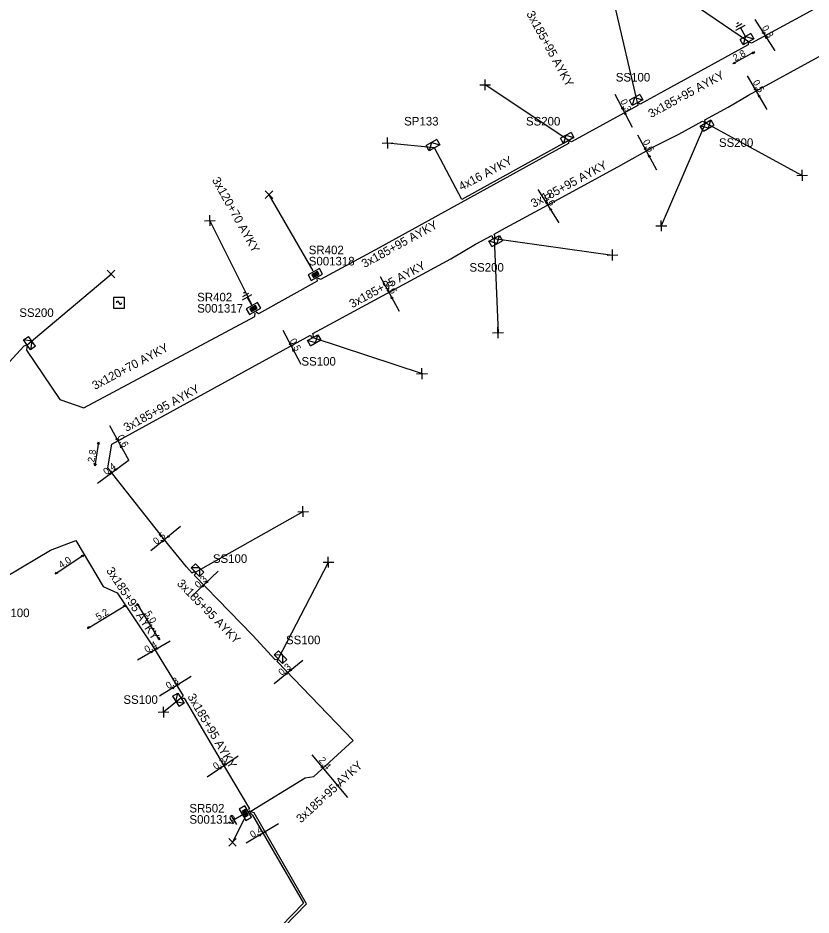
# Model space of a CAD drawing. Extents: x -762500 to -761285, y -1155006 to -1154135.
# Drawn here: x -761820.3 to -761728.2, y -1154763.7 to -1154659.6 of the extents above; entities that cross this region are included whole.
import ezdxf

# ---------------------------------------------------------------- set-up
doc = ezdxf.new("R2010")
doc.units = 0
for name, color, linetype in [('Vrstva 15', 7, 'Continuous'), ('Vrstva 28', 7, 'Continuous'), ('Vrstva 29', 7, 'Continuous'), ('Vrstva 30', 7, 'Continuous'), ('Vrstva 31', 7, 'Continuous'), ('Vrstva 33', 7, 'Continuous'), ('Vrstva 34', 7, 'Continuous'), ('Vrstva 40', 7, 'Continuous'), ('Vrstva 5', 7, 'Continuous'), ('Vrstva 59', 7, 'Continuous'), ('Vrstva 6', 7, 'Continuous')]:
    doc.layers.add(name, color=color, linetype=linetype)

msp = doc.modelspace()

# ---------------------------------------------------------------- linework, layer by layer
at = {"layer": 'Vrstva 15'}
for points in [[(-761736.967, -1154661.052), (-761735.874, -1154660.446)], [(-761736.906, -1154660.664), (-761736.218, -1154660.282)], [(-761736.84, -1154660.267), (-761736.723, -1154660.203)], [(-761736.723, -1154660.203), (-761736.611, -1154660.14)], [(-761735.814, -1154661.842), (-761736.42, -1154660.749)], [(-761794.227, -1154692.312), (-761793.134, -1154691.706)], [(-761794.166, -1154691.924), (-761793.478, -1154691.542)], [(-761794.099, -1154691.527), (-761793.983, -1154691.462)], [(-761793.983, -1154691.462), (-761793.871, -1154691.4)], [(-761793.074, -1154693.102), (-761793.68, -1154692.009)], [(-761794.126, -1154751.994), (-761795.198, -1154752.638)], [(-761795.734, -1154752.96), (-761795.8, -1154752.85)], [(-761795.665, -1154753.074), (-761795.734, -1154752.96)], [(-761795.266, -1154753.126), (-761795.671, -1154752.451)], [(-761794.876, -1154753.173), (-761795.52, -1154752.102)]]:
    msp.add_lwpolyline(points, dxfattribs=at)
at = {"layer": 'Vrstva 28'}
for points in [[(-761785.287, -1154688.704), (-761786.599, -1154689.432)], [(-761786.599, -1154689.432), (-761786.236, -1154690.088)], [(-761786.236, -1154690.088), (-761784.924, -1154689.36)], [(-761785.521, -1154689.05), (-761786.172, -1154689.411)], [(-761786.172, -1154689.411), (-761785.989, -1154689.741)], [(-761785.54, -1154689.114), (-761786.108, -1154689.429)], [(-761786.108, -1154689.429), (-761785.971, -1154689.677)], [(-761785.558, -1154689.179), (-761786.044, -1154689.448)], [(-761786.044, -1154689.448), (-761785.952, -1154689.613)], [(-761785.989, -1154689.741), (-761785.338, -1154689.381)], [(-761785.577, -1154689.243), (-761785.979, -1154689.466)], [(-761785.979, -1154689.466), (-761785.934, -1154689.549)], [(-761785.971, -1154689.677), (-761785.402, -1154689.362)], [(-761785.952, -1154689.613), (-761785.467, -1154689.344)], [(-761785.934, -1154689.549), (-761785.531, -1154689.325)], [(-761785.59, -1154689.304), (-761785.92, -1154689.487)], [(-761785.531, -1154689.325), (-761785.577, -1154689.243)], [(-761785.467, -1154689.344), (-761785.558, -1154689.179)], [(-761785.402, -1154689.362), (-761785.54, -1154689.114)], [(-761785.338, -1154689.381), (-761785.521, -1154689.05)], [(-761784.924, -1154689.36), (-761785.287, -1154688.704)], [(-761792.468, -1154692.644), (-761793.78, -1154693.372)], [(-761792.104, -1154693.3), (-761792.468, -1154692.644)], [(-761793.78, -1154693.372), (-761793.416, -1154694.028)], [(-761793.416, -1154694.028), (-761792.104, -1154693.3)], [(-761792.702, -1154692.99), (-761793.353, -1154693.351)], [(-761793.353, -1154693.351), (-761793.169, -1154693.681)], [(-761792.72, -1154693.054), (-761793.288, -1154693.369)], [(-761793.288, -1154693.369), (-761793.151, -1154693.617)], [(-761792.739, -1154693.119), (-761793.224, -1154693.388)], [(-761793.224, -1154693.388), (-761793.133, -1154693.553)], [(-761793.169, -1154693.681), (-761792.519, -1154693.321)], [(-761792.757, -1154693.183), (-761793.16, -1154693.406)], [(-761793.16, -1154693.406), (-761793.114, -1154693.489)], [(-761793.151, -1154693.617), (-761792.583, -1154693.302)], [(-761793.133, -1154693.553), (-761792.647, -1154693.284)], [(-761793.114, -1154693.489), (-761792.711, -1154693.265)], [(-761792.77, -1154693.244), (-761793.101, -1154693.427)], [(-761792.711, -1154693.265), (-761792.757, -1154693.183)], [(-761792.647, -1154693.284), (-761792.739, -1154693.119)], [(-761792.583, -1154693.302), (-761792.72, -1154693.054)], [(-761792.519, -1154693.321), (-761792.702, -1154692.99)], [(-761793.962, -1154751.017), (-761794.605, -1154751.403)], [(-761794.605, -1154751.403), (-761793.833, -1154752.689)], [(-761793.928, -1154751.43), (-761794.252, -1154751.625)], [(-761794.252, -1154751.625), (-761793.868, -1154752.263)], [(-761793.944, -1154751.495), (-761794.187, -1154751.641)], [(-761794.187, -1154751.641), (-761793.852, -1154752.198)], [(-761793.96, -1154751.56), (-761794.122, -1154751.657)], [(-761794.122, -1154751.657), (-761793.836, -1154752.133)], [(-761793.976, -1154751.625), (-761794.057, -1154751.673)], [(-761794.057, -1154751.673), (-761793.82, -1154752.068)], [(-761793.995, -1154751.685), (-761793.801, -1154752.009)], [(-761793.739, -1154752.02), (-761793.976, -1154751.625)], [(-761793.19, -1154752.303), (-761793.962, -1154751.017)], [(-761793.674, -1154752.036), (-761793.96, -1154751.56)], [(-761793.609, -1154752.052), (-761793.944, -1154751.495)], [(-761793.544, -1154752.068), (-761793.928, -1154751.43)], [(-761793.852, -1154752.198), (-761793.609, -1154752.052)], [(-761793.836, -1154752.133), (-761793.674, -1154752.036)], [(-761793.82, -1154752.068), (-761793.739, -1154752.02)], [(-761793.868, -1154752.263), (-761793.544, -1154752.068)], [(-761793.833, -1154752.689), (-761793.19, -1154752.303)]]:
    msp.add_lwpolyline(points, dxfattribs=at)
at = {"layer": 'Vrstva 31'}
for points in [[(-761735.224, -1154661.447), (-761736.449, -1154662.126)], [(-761735.224, -1154661.447), (-761734.885, -1154662.059), (-761736.109, -1154662.738), (-761736.449, -1154662.126)], [(-761735.837, -1154661.786), (-761736.109, -1154662.738)], [(-761735.837, -1154661.786), (-761734.885, -1154662.059)], [(-761748.095, -1154668.497), (-761749.32, -1154669.176)], [(-761748.095, -1154668.497), (-761747.756, -1154669.109), (-761748.98, -1154669.788), (-761749.32, -1154669.176)], [(-761748.707, -1154668.836), (-761748.98, -1154669.788)], [(-761748.707, -1154668.836), (-761747.756, -1154669.109)], [(-761740.729, -1154672.768), (-761741.079, -1154672.162), (-761739.866, -1154671.462), (-761739.516, -1154672.068)], [(-761740.122, -1154672.418), (-761739.866, -1154671.462)], [(-761756.085, -1154672.897), (-761757.309, -1154673.576)], [(-761756.085, -1154672.897), (-761755.746, -1154673.509), (-761756.97, -1154674.188), (-761757.309, -1154673.576)], [(-761740.122, -1154672.418), (-761741.079, -1154672.162)], [(-761740.729, -1154672.768), (-761739.516, -1154672.068)], [(-761771.665, -1154673.737), (-761772.89, -1154674.416)], [(-761771.665, -1154673.737), (-761771.326, -1154674.349), (-761772.55, -1154675.028), (-761772.89, -1154674.416)], [(-761756.697, -1154673.236), (-761756.97, -1154674.188)], [(-761756.697, -1154673.236), (-761755.746, -1154673.509)], [(-761772.277, -1154674.076), (-761772.55, -1154675.028)], [(-761772.277, -1154674.076), (-761771.326, -1154674.349)], [(-761765.285, -1154686.143), (-761765.624, -1154685.531), (-761764.4, -1154684.852), (-761764.06, -1154685.464)], [(-761764.673, -1154685.804), (-761764.4, -1154684.852)], [(-761764.673, -1154685.804), (-761765.624, -1154685.531)], [(-761765.285, -1154686.143), (-761764.06, -1154685.464)], [(-761818.253, -1154697.704), (-761818.827, -1154698.105), (-761819.63, -1154696.958), (-761819.056, -1154696.557)], [(-761818.253, -1154697.704), (-761819.056, -1154696.557)], [(-761786.345, -1154697.654), (-761786.685, -1154697.041), (-761785.46, -1154696.363), (-761785.121, -1154696.975)], [(-761785.733, -1154697.314), (-761785.46, -1154696.363)], [(-761818.655, -1154697.13), (-761819.63, -1154696.958)], [(-761818.655, -1154697.13), (-761818.827, -1154698.105)], [(-761785.733, -1154697.314), (-761786.685, -1154697.041)], [(-761786.345, -1154697.654), (-761785.121, -1154696.975)], [(-761798.698, -1154723.912), (-761799.193, -1154724.407), (-761800.183, -1154723.417), (-761799.688, -1154722.922)], [(-761799.193, -1154723.417), (-761800.183, -1154723.417)], [(-761798.698, -1154723.912), (-761799.688, -1154722.922)], [(-761799.193, -1154723.417), (-761799.193, -1154724.407)], [(-761789.088, -1154734.029), (-761789.591, -1154734.515), (-761790.564, -1154733.508), (-761790.06, -1154733.022)], [(-761789.088, -1154734.029), (-761790.06, -1154733.022)], [(-761789.574, -1154733.525), (-761790.564, -1154733.508)], [(-761789.574, -1154733.525), (-761789.591, -1154734.515)], [(-761802.327, -1154738.295), (-761801.733, -1154737.924), (-761800.991, -1154739.111), (-761801.585, -1154739.482)], [(-761802.327, -1154738.295), (-761801.585, -1154739.482)], [(-761801.956, -1154738.889), (-761801.733, -1154737.924)], [(-761801.956, -1154738.889), (-761800.991, -1154739.111)]]:
    msp.add_lwpolyline(points, dxfattribs=at)
at = {"layer": 'Vrstva 34'}
for points in [[(-761766.685, -1154667.391), (-761765.435, -1154667.369)], [(-761766.049, -1154668.005), (-761766.071, -1154666.755)], [(-761777.369, -1154674.755), (-761777.391, -1154673.505)], [(-761778.005, -1154674.141), (-761776.755, -1154674.119)], [(-761729.875, -1154677.891), (-761728.625, -1154677.869)], [(-761729.239, -1154678.505), (-761729.261, -1154677.255)], [(-761791.572, -1154679.688), (-761790.688, -1154680.572)], [(-761791.572, -1154680.572), (-761790.688, -1154679.688)], [(-761798.625, -1154683.141), (-761797.375, -1154683.119)], [(-761797.989, -1154683.755), (-761798.011, -1154682.505)], [(-761745.599, -1154684.355), (-761745.621, -1154683.105)], [(-761746.235, -1154683.741), (-761744.985, -1154683.719)], [(-761751.269, -1154687.745), (-761751.291, -1154686.495)], [(-761751.905, -1154687.131), (-761750.655, -1154687.109)], [(-761809.922, -1154688.898), (-761809.038, -1154689.782)], [(-761809.922, -1154689.782), (-761809.038, -1154688.898)], [(-761807.926, -1154692.036), (-761809.176, -1154692.036)], [(-761809.176, -1154692.036), (-761809.176, -1154693.286)], [(-761808.551, -1154692.661), (-761808.552, -1154692.645), (-761808.554, -1154692.63), (-761808.558, -1154692.614), (-761808.564, -1154692.599), (-761808.571, -1154692.585), (-761808.58, -1154692.572), (-761808.59, -1154692.559), (-761808.601, -1154692.548), (-761808.613, -1154692.538), (-761808.627, -1154692.529), (-761808.641, -1154692.522), (-761808.656, -1154692.516), (-761808.671, -1154692.512), (-761808.687, -1154692.509), (-761808.703, -1154692.508), (-761808.719, -1154692.509), (-761808.735, -1154692.511), (-761808.75, -1154692.515), (-761808.765, -1154692.521), (-761808.779, -1154692.528), (-761808.793, -1154692.537), (-761808.805, -1154692.547), (-761808.817, -1154692.558), (-761808.827, -1154692.57), (-761808.835, -1154692.584), (-761808.843, -1154692.598), (-761808.849, -1154692.613), (-761808.853, -1154692.628), (-761808.855, -1154692.644), (-761808.856, -1154692.66), (-761808.856, -1154692.661)], [(-761808.551, -1154692.661), (-761808.551, -1154692.677), (-761808.548, -1154692.693), (-761808.545, -1154692.708), (-761808.539, -1154692.723), (-761808.532, -1154692.737), (-761808.524, -1154692.75), (-761808.515, -1154692.763), (-761808.504, -1154692.774), (-761808.492, -1154692.784), (-761808.479, -1154692.793), (-761808.465, -1154692.8), (-761808.45, -1154692.806), (-761808.435, -1154692.811), (-761808.42, -1154692.813), (-761808.404, -1154692.814), (-761808.388, -1154692.814), (-761808.373, -1154692.812), (-761808.357, -1154692.808), (-761808.343, -1154692.803), (-761808.329, -1154692.796), (-761808.315, -1154692.787), (-761808.303, -1154692.778), (-761808.292, -1154692.767), (-761808.281, -1154692.755), (-761808.273, -1154692.742), (-761808.265, -1154692.728), (-761808.259, -1154692.713), (-761808.255, -1154692.698), (-761808.252, -1154692.683), (-761808.251, -1154692.667), (-761808.251, -1154692.666)], [(-761807.926, -1154693.286), (-761807.926, -1154692.036)], [(-761809.176, -1154693.286), (-761807.926, -1154693.286)], [(-761764.549, -1154696.755), (-761764.571, -1154695.505)], [(-761765.185, -1154696.141), (-761763.935, -1154696.119)], [(-761774.005, -1154700.891), (-761772.755, -1154700.869)], [(-761773.369, -1154701.505), (-761773.391, -1154700.255)], [(-761787.179, -1154717.505), (-761787.201, -1154716.255)], [(-761787.815, -1154716.891), (-761786.565, -1154716.869)], [(-761784.875, -1154722.761), (-761783.625, -1154722.739)], [(-761784.239, -1154723.375), (-761784.261, -1154722.125)], [(-761803.369, -1154740.755), (-761803.391, -1154739.505)], [(-761804.005, -1154740.141), (-761802.755, -1154740.119)], [(-761795.822, -1154754.808), (-761794.938, -1154755.692)], [(-761795.822, -1154755.692), (-761794.938, -1154754.808)]]:
    msp.add_lwpolyline(points, dxfattribs=at)
at = {"layer": 'Vrstva 40'}
for points in [[(-761734.75, -1154659.81), (-761732.43, -1154663.43)], [(-761734.8, -1154663.57), (-761737.29, -1154664.95)], [(-761733.34, -1154670.26), (-761735.61, -1154666.33)], [(-761748.95, -1154672.34), (-761750.96, -1154668.51)], [(-761746.13, -1154677.28), (-761748.35, -1154673.21)], [(-761757.47, -1154683.4), (-761759.89, -1154679.52)], [(-761775.99, -1154693.67), (-761778.19, -1154689.66)], [(-761789.55, -1154695.85), (-761787.44, -1154699.8)], [(-761809.67, -1154706.9), (-761807.42, -1154710.96)], [(-761810.92, -1154708.81), (-761811.36, -1154711.56)], [(-761811.07, -1154713.58), (-761807.5, -1154710.94)], [(-761801.43, -1154718.6), (-761804.86, -1154721.45)], [(-761815.95, -1154724.11), (-761812.64, -1154721.91)], [(-761800.16, -1154726.76), (-761797.04, -1154723.78)], [(-761812.22, -1154730.42), (-761807.76, -1154727.72)], [(-761803.84, -1154731.76), (-761806.46, -1154727.54)], [(-761806.4, -1154734.07), (-761802.62, -1154731.85)], [(-761790.54, -1154736.83), (-761787.23, -1154734.1)], [(-761803.85, -1154738.26), (-761800.16, -1154735.98)], [(-761798.31, -1154747.65), (-761794.72, -1154745.22)], [(-761782.01, -1154750.04), (-761786.13, -1154745.09)], [(-761790.04, -1154753.1), (-761793.81, -1154755.35)]]:
    msp.add_lwpolyline(points, dxfattribs=at)
for points in [[(-761733.669, -1154661.492), (-761733.892, -1154661.341), (-761733.717, -1154661.227)], [(-761733.511, -1154661.738), (-761733.288, -1154661.889), (-761733.463, -1154662.003)], [(-761734.797, -1154663.569), (-761734.964, -1154663.781), (-761735.065, -1154663.598)], [(-761737.292, -1154664.951), (-761737.125, -1154664.739), (-761737.024, -1154664.922)], [(-761734.609, -1154668.062), (-761734.824, -1154667.899), (-761734.643, -1154667.795)], [(-761734.341, -1154668.528), (-761734.126, -1154668.691), (-761734.307, -1154668.795)], [(-761750.029, -1154670.282), (-761750.238, -1154670.112), (-761750.054, -1154670.014)], [(-761749.881, -1154670.568), (-761749.672, -1154670.739), (-761749.857, -1154670.837)], [(-761747.389, -1154674.972), (-761747.601, -1154674.806), (-761747.418, -1154674.704)], [(-761747.091, -1154675.518), (-761746.879, -1154675.684), (-761747.062, -1154675.786)], [(-761758.829, -1154681.222), (-761759.052, -1154681.071), (-761758.877, -1154680.957)], [(-761758.531, -1154681.698), (-761758.308, -1154681.849), (-761758.483, -1154681.963)], [(-761777.229, -1154691.412), (-761777.441, -1154691.246), (-761777.258, -1154691.144)], [(-761776.951, -1154691.918), (-761776.739, -1154692.084), (-761776.922, -1154692.186)], [(-761788.609, -1154697.612), (-761788.821, -1154697.446), (-761788.638, -1154697.344)], [(-761788.381, -1154698.038), (-761788.169, -1154698.204), (-761788.352, -1154698.306)], [(-761810.919, -1154708.807), (-761810.855, -1154709.069), (-761811.061, -1154709.037)], [(-761808.699, -1154708.652), (-761808.911, -1154708.486), (-761808.728, -1154708.384)], [(-761808.391, -1154709.208), (-761808.179, -1154709.374), (-761808.362, -1154709.476)], [(-761811.36, -1154711.562), (-761811.425, -1154711.301), (-761811.218, -1154711.333)], [(-761809.458, -1154712.389), (-761809.594, -1154712.622), (-761809.719, -1154712.455)], [(-761809.112, -1154712.131), (-761808.976, -1154711.898), (-761808.851, -1154712.065)], [(-761802.972, -1154719.882), (-761802.849, -1154719.642), (-761802.714, -1154719.802)], [(-761803.318, -1154720.169), (-761803.441, -1154720.408), (-761803.576, -1154720.248)], [(-761812.638, -1154721.909), (-761812.785, -1154722.134), (-761812.902, -1154721.961)], [(-761815.952, -1154724.111), (-761815.805, -1154723.886), (-761815.688, -1154724.059)], [(-761798.482, -1154725.162), (-761798.376, -1154724.914), (-761798.231, -1154725.064)], [(-761798.708, -1154725.378), (-761798.814, -1154725.626), (-761798.959, -1154725.476)], [(-761807.758, -1154727.718), (-761807.914, -1154727.939), (-761808.024, -1154727.762)], [(-761806.461, -1154727.537), (-761806.241, -1154727.693), (-761806.418, -1154727.804)], [(-761812.223, -1154730.421), (-761812.067, -1154730.2), (-761811.957, -1154730.378)], [(-761803.839, -1154731.762), (-761804.059, -1154731.607), (-761803.882, -1154731.496)], [(-761804.678, -1154733.059), (-761804.837, -1154733.277), (-761804.945, -1154733.097)], [(-761804.342, -1154732.861), (-761804.183, -1154732.643), (-761804.075, -1154732.823)], [(-761788.772, -1154735.372), (-761788.649, -1154735.132), (-761788.514, -1154735.292)], [(-761788.998, -1154735.559), (-761789.121, -1154735.798), (-761789.256, -1154735.638)], [(-761802.148, -1154737.209), (-761802.303, -1154737.429), (-761802.414, -1154737.252)], [(-761801.862, -1154737.031), (-761801.707, -1154736.811), (-761801.596, -1154736.988)], [(-761796.648, -1154746.529), (-761796.792, -1154746.757), (-761796.911, -1154746.586)], [(-761796.372, -1154746.341), (-761796.228, -1154746.113), (-761796.109, -1154746.284)], [(-761784.849, -1154746.632), (-761785.089, -1154746.509), (-761784.928, -1154746.374)], [(-761783.292, -1154748.498), (-761783.052, -1154748.621), (-761783.212, -1154748.755)], [(-761791.762, -1154754.121), (-761791.603, -1154753.903), (-761791.495, -1154754.082)], [(-761792.088, -1154754.319), (-761792.247, -1154754.536), (-761792.355, -1154754.357)]]:
    msp.add_lwpolyline(points, close=True, dxfattribs=at)
at = {"layer": 'Vrstva 5'}
for points in [[(-761702.95, -1154635.12), (-761702.54, -1154635.17), (-761702.16, -1154635.93), (-761701.48, -1154638.13), (-761701.49, -1154641.07), (-761702.39, -1154643.28), (-761703.91, -1154644.9), (-761707.18, -1154646.86), (-761716.24, -1154652.23), (-761729.56, -1154659.53), (-761735.14, -1154662.55), (-761735.5, -1154662.4), (-761735.51, -1154662.76), (-761748.08, -1154669.62), (-761748.37, -1154669.45)], [(-761793.5, -1154751.54), (-761793.24, -1154751.61), (-761786.93, -1154747.76), (-761785.94, -1154747.61), (-761781.36, -1154743.43), (-761790.21, -1154734.27), (-761790.08, -1154734.01), (-761790.41, -1154734.06), (-761793.01, -1154731.24), (-761799.85, -1154724.25), (-761799.69, -1154724.1), (-761799.69, -1154723.91), (-761799.9, -1154723.89), (-761800.05, -1154724.03), (-761800.74, -1154723.27), (-761802.79, -1154720.79), (-761809.84, -1154711.8), (-761809.4, -1154709.05), (-761786.31, -1154696.42), (-761786.25, -1154696.63), (-761786.07, -1154696.7), (-761785.97, -1154696.5), (-761786.05, -1154696.24), (-761783.12, -1154694.63), (-761770.03, -1154687.55), (-761767.16, -1154685.85), (-761765.28, -1154684.87), (-761765.19, -1154685.13), (-761765.01, -1154685.19), (-761764.91, -1154685.03), (-761765.01, -1154684.72), (-761763.71, -1154683.96), (-761759.76, -1154681.84), (-761750.64, -1154676.91), (-761746.35, -1154674.5), (-761743.59, -1154673.11), (-761740.81, -1154671.6), (-761740.47, -1154671.81), (-761740.56, -1154671.44), (-761737.84, -1154669.99), (-761735.5, -1154668.57), (-761723.67, -1154662.14)], [(-761748.37, -1154669.45), (-761748.33, -1154669.77), (-761756.02, -1154673.98), (-761756.36, -1154673.85)], [(-761756.36, -1154673.85), (-761756.37, -1154674.19), (-761778.35, -1154686.29), (-761785.17, -1154689.95), (-761785.46, -1154689.8)], [(-761756.36, -1154673.85), (-761756.67, -1154674.01), (-761768.76, -1154680.67), (-761771.94, -1154674.69)], [(-761785.58, -1154689.86), (-761785.54, -1154690.15), (-761792.37, -1154693.96), (-761792.64, -1154693.75)], [(-761834.1, -1154709.78), (-761833.57, -1154710.06), (-761827.8, -1154706.59), (-761819.55, -1154697.65), (-761819.23, -1154697.53), (-761819.28, -1154698.14), (-761815.44, -1154703.86), (-761812.64, -1154704.83), (-761792.79, -1154694.24), (-761792.75, -1154693.81)], [(-761825.21, -1154727.44), (-761825.16, -1154727.17), (-761825.43, -1154726.65), (-761816.51, -1154721.34), (-761813.58, -1154720.25), (-761810.39, -1154725.58), (-761808.75, -1154726.29), (-761804.74, -1154732.32), (-761801.12, -1154738.26), (-761801.36, -1154738.52), (-761800.98, -1154738.53), (-761796.81, -1154745.62), (-761793.41, -1154751.37), (-761793.57, -1154751.43)], [(-761793.37, -1154751.76), (-761793.05, -1154752.07), (-761787.15, -1154762.31), (-761806.36, -1154782.09), (-761826.62, -1154799.89), (-761862.11, -1154822.83), (-761911.18, -1154851.08), (-761920.77, -1154856.64), (-761929.42, -1154842.63), (-761938.89, -1154848.44), (-761944.86, -1154847.05), (-761973.05, -1154830.1), (-761980.58, -1154827.44), (-761983.64, -1154827.88), (-761985.29, -1154827.77), (-762002.6, -1154821.09), (-762002.75, -1154820.78), (-762006.65, -1154819.22), (-762005.33, -1154816.4)], [(-761747.33, -1154791.4), (-761747.29, -1154791.37), (-761752.76, -1154783.1), (-761763.87, -1154789.21), (-761784.99, -1154800.86), (-761785.56, -1154801.09), (-761791.75, -1154804.84), (-761805.98, -1154782.13), (-761786.78, -1154762.36), (-761792.86, -1154751.8), (-761793.44, -1154751.65)]]:
    msp.add_lwpolyline(points, dxfattribs=at)
at = {"layer": 'Vrstva 59'}
for points in [[(-761735.5, -1154662.4), (-761746.13, -1154655.13)], [(-761748.37, -1154669.45), (-761751.06, -1154658)], [(-761756.36, -1154673.85), (-761766.06, -1154667.38)], [(-761740.47, -1154671.81), (-761745.61, -1154683.73)], [(-761740.47, -1154671.81), (-761729.25, -1154677.88)], [(-761771.94, -1154674.69), (-761777.38, -1154674.13)], [(-761786.03, -1154688.95), (-761791.13, -1154680.13)], [(-761793.15, -1154692.87), (-761798, -1154683.13)], [(-761765.01, -1154685.19), (-761751.28, -1154687.12)], [(-761765.01, -1154685.19), (-761764.56, -1154696.13)], [(-761819.23, -1154697.53), (-761809.48, -1154689.34)], [(-761786.07, -1154696.7), (-761773.38, -1154700.88)], [(-761799.69, -1154723.91), (-761787.19, -1154716.88)], [(-761790.08, -1154734.01), (-761784.25, -1154722.75)], [(-761801.36, -1154738.52), (-761803.38, -1154740.13)], [(-761794.05, -1154752.6), (-761795.38, -1154755.25)]]:
    msp.add_lwpolyline(points, dxfattribs=at)

# ---------------------------------------------------------------- texts
at = {"layer": 'Vrstva 29'}
for s, p in [('S001318', (-761786.53, -1154688.33)), ('S001317', (-761799.48, -1154693.8)), ('S001319', (-761800.38, -1154753.08))]:
    msp.add_text(s, height=0.9943, dxfattribs=at).set_placement(p)
at = {"layer": 'Vrstva 30'}
for s, p in [('SR402', (-761786.53, -1154687.03)), ('SR402', (-761799.48, -1154692.5)), ('SR502', (-761800.38, -1154751.78))]:
    msp.add_text(s, height=0.9943, dxfattribs=at).set_placement(p)
at = {"layer": 'Vrstva 33'}
for s, p in [('SS100', (-761750.89, -1154667)), ('SP133', (-761775.46, -1154672.1)), ('SS200', (-761761.32, -1154672.1)), ('SS200', (-761738.92, -1154674.58)), ('SS200', (-761767.88, -1154689.05)), ('SS200', (-761820.13, -1154694.3)), ('SS100', (-761787.38, -1154699.95)), ('SS100', (-761797.66, -1154722.83)), ('SS100', (-761822.93, -1154729.12)), ('SS100', (-761789.17, -1154732.26)), ('SS100', (-761808.04, -1154739.18))]:
    msp.add_text(s, height=0.9943, dxfattribs=at).set_placement(p)
at = {"layer": 'Vrstva 40'}
for s, rotation, p in [('0,3', 302.61377, (-761733.98, -1154660.78)), ('2,8', 28.99603, (-761737.03, -1154664.67)), ('0,5', 299.87316, (-761735.03, -1154667.08)), ('0,3', 297.7046, (-761750.41, -1154669.29)), ('0,6', 298.61325, (-761747.79, -1154673.98)), ('0,6', 302.00292, (-761759.29, -1154680.26)), ('0,6', 298.76726, (-761777.64, -1154690.42)), ('0,5', 298.13589, (-761788.77, -1154697.05)), ('0,6', 298.96488, (-761808.8, -1154708.22)), ('2,8', 80.90948, (-761811.43, -1154711.21)), ('0,4', 36.6027, (-761810.03, -1154712.67)), ('0,5', 39.63654, (-761804.21, -1154720.75)), ('4,0', 33.60968, (-761815.25, -1154723.5)), ('0,3', 43.72524, (-761799.33, -1154725.81)), ('5,2', 31.1901, (-761810.96, -1154729.51)), ('5,0', 301.80715, (-761805.6, -1154728.68)), ('0,4', 30.47061, (-761805.32, -1154733.29)), ('0,3', 39.55179, (-761789.66, -1154735.95)), ('0,3', 31.81767, (-761802.82, -1154737.49)), ('0,3', 34.15319, (-761797.32, -1154746.84)), ('2,4', 309.74168, (-761785.43, -1154745.74)), ('0,4', 30.85546, (-761793.06, -1154754.76))]:
    msp.add_text(s, height=0.7954, rotation=rotation, dxfattribs=at).set_placement(p)
at = {"layer": 'Vrstva 6'}
for s, height, rotation, p in [('3x185+95 AYKY', 0.99429, 298.71428, (-761761.3, -1154659.13)), ('3x185+95 AYKY', 0.99429, 28.60471, (-761746.8, -1154671.25)), ('4x16 AYKY', 0.9943, 28.00934, (-761768.8, -1154679.68)), ('3x185+95 AYKY', 0.99428, 28.39433, (-761760.42, -1154681.66)), ('3x120+70 AYKY', 0.99429, 299.22683, (-761797.8, -1154678.42)), ('3x185+95 AYKY', 0.99429, 28.84501, (-761780.06, -1154688.65)), ('3x185+95 AYKY', 0.99429, 28.40767, (-761781.49, -1154693.3)), ('3x120+70 AYKY', 0.99429, 28.08148, (-761811.35, -1154702.78)), ('3x185+95 AYKY', 0.99429, 28.68673, (-761807.7, -1154707.65)), ('3x185+95 AYKY', 0.99429, 303.62424, (-761810.08, -1154723.72)), ('3x185+95 AYKY', 0.99429, 314.39098, (-761801.9, -1154725.3)), ('3x185+95 AYKY', 0.99429, 300.43694, (-761800.65, -1154738.34)), ('3x185+95 AYKY', 0.99428, 42.38557, (-761787.44, -1154753.05))]:
    msp.add_text(s, height=height, rotation=rotation, dxfattribs=at).set_placement(p)

doc.saveas('drawing.dxf')
